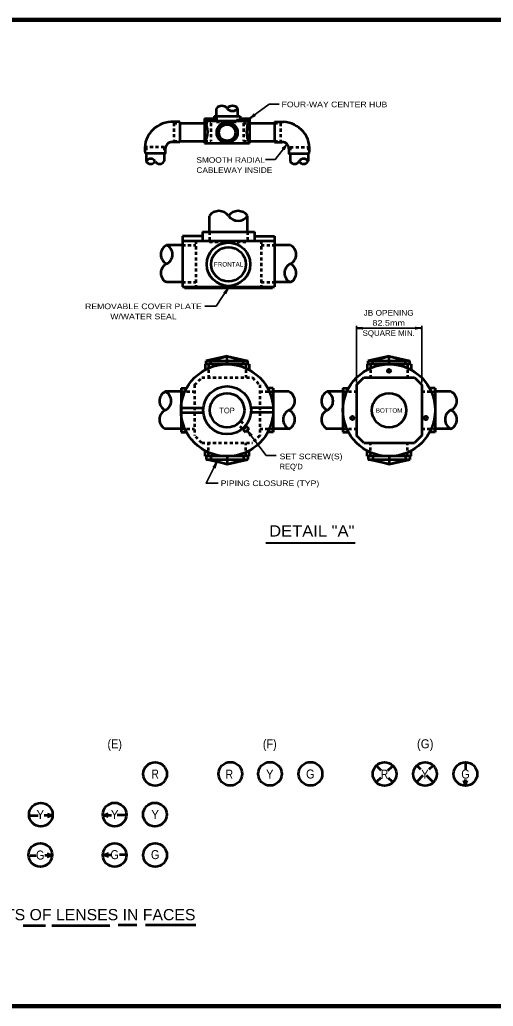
# Model space of a CAD drawing. Extents: x -382 to 473, y -132 to 412.
# Drawn here: x -79 to 174, y -120 to 406 of the extents above; entities that cross this region are included whole.
import ezdxf
from ezdxf.enums import TextEntityAlignment as Align

# ---------------------------------------------------------------- set-up
doc = ezdxf.new("R2010")
doc.units = 0
doc.header["$LTSCALE"] = 1.1
doc.linetypes.add('SHORT_DASHED', pattern=[2.7, 1.5, -1.2])
doc.layers.add('1', color=7, linetype='Continuous', lineweight=53)

msp = doc.modelspace()

# ---------------------------------------------------------------- linework, layer by layer
at = {"layer": '1'}
for p, q in [((26.07, 354.293), (26.07, 358.493)), ((37.47, 354.293), (37.47, 358.493)), ((19.77, 353.093), (19.77, 339.893)), ((19.77, 353.093), (24.87, 353.093)), ((24.87, 354.293), (38.67, 354.293)), ((24.87, 354.293), (24.87, 351.893)), ((38.67, 354.293), (38.67, 351.893)), ((38.67, 353.093), (43.77, 353.093)), ((43.77, 353.093), (43.77, 339.893)), ((6.57, 351.293), (1.77, 351.293)), ((6.57, 351.293), (6.57, 340.493)), ((6.57, 350.693), (19.77, 350.693)), ((19.77, 351.893), (43.77, 351.893)), ((43.77, 350.693), (56.97, 350.693)), ((56.97, 351.293), (56.97, 340.493)), ((56.97, 351.293), (61.77, 351.293)), ((6.57, 340.493), (2.37, 340.493)), ((6.57, 341.093), (19.77, 341.093)), ((19.77, 339.893), (43.77, 339.893)), ((43.77, 341.093), (56.97, 341.093)), ((56.97, 340.493), (61.17, 340.493)), ((-11.43, 334.493), (-11.43, 330.293)), ((-1.83, 334.493), (-1.83, 330.293)), ((65.37, 334.493), (65.37, 330.293)), ((74.97, 334.493), (74.97, 330.293)), ((22.298, 292.745), (22.298, 301.145)), ((42.698, 292.745), (42.698, 301.145)), ((18.698, 290.345), (7.898, 290.345)), ((7.898, 290.345), (7.898, 263.345)), ((18.698, 292.745), (46.298, 292.745)), ((18.698, 292.745), (18.698, 287.945)), ((46.298, 292.745), (46.298, 287.945)), ((46.298, 290.345), (57.098, 290.345)), ((57.098, 290.345), (57.098, 263.345)), ((7.898, 285.545), (-0.502, 285.545)), ((7.898, 287.945), (57.098, 287.945)), ((65.498, 285.545), (57.098, 285.545)), ((7.898, 265.745), (-0.502, 265.745)), ((7.898, 263.345), (57.098, 263.345)), ((9.098, 262.745), (9.098, 263.345)), ((55.898, 262.745), (55.898, 263.345)), ((65.498, 265.745), (57.098, 265.745)), ((9.098, 262.745), (55.898, 262.745)), ((31.77, 226.309), (42.87, 223.909)), ((118.17, 226.309), (129.27, 223.909)), ((20.07, 222.109), (20.07, 219.172)), ((43.47, 222.109), (20.07, 222.109)), ((20.67, 222.109), (20.67, 223.909)), ((20.67, 223.909), (42.87, 223.909)), ((23.07, 222.109), (23.07, 223.909)), ((40.47, 222.109), (40.47, 223.909)), ((42.87, 222.109), (42.87, 223.909)), ((43.47, 222.109), (43.47, 219.125)), ((106.47, 222.109), (106.47, 219.172)), ((129.87, 222.109), (106.47, 222.109)), ((107.07, 222.109), (107.07, 223.909)), ((107.07, 223.909), (129.27, 223.909)), ((109.47, 222.109), (109.47, 223.909)), ((126.87, 222.109), (126.87, 223.909)), ((129.27, 222.109), (129.27, 223.909)), ((129.87, 222.109), (129.87, 219.125)), ((100.77, 211.053), (104.67, 214.909)), ((100.77, 211.053), (100.77, 184.053)), ((104.67, 214.909), (131.67, 214.909)), ((131.67, 214.909), (135.57, 211.053)), ((135.57, 211.053), (135.57, 184.053)), ((7.17, 207.453), (-1.23, 207.453)), ((7.17, 209.253), (7.17, 185.853)), ((7.17, 209.253), (10.154, 209.253)), ((56.37, 209.253), (53.385, 209.253)), ((56.37, 209.253), (56.37, 185.853)), ((64.77, 207.453), (56.37, 207.453)), ((93.57, 207.453), (85.17, 207.453)), ((93.57, 209.253), (93.57, 185.853)), ((93.57, 209.253), (96.554, 209.253)), ((142.77, 209.253), (139.785, 209.253)), ((142.77, 209.253), (142.77, 185.853)), ((151.17, 207.453), (142.77, 207.453)), ((7.17, 198.753), (19.05, 198.753)), ((7.17, 196.353), (19.042, 196.353)), ((56.37, 198.753), (44.489, 198.753)), ((56.37, 196.353), (44.497, 196.353)), ((7.17, 187.653), (-1.23, 187.653)), ((7.17, 185.853), (10.106, 185.853)), ((40.457, 187.188), (39.949, 187.69)), ((42.142, 188.893), (40.351, 187.082)), ((40.351, 187.082), (41.631, 185.816)), ((41.543, 189.274), (42.036, 188.786)), ((43.422, 187.627), (41.631, 185.816)), ((42.142, 188.893), (43.422, 187.627)), ((56.37, 185.853), (53.433, 185.853)), ((64.77, 187.653), (56.37, 187.653)), ((93.57, 187.653), (85.17, 187.653)), ((93.57, 185.853), (96.506, 185.853)), ((142.77, 185.853), (139.833, 185.853)), ((151.17, 187.653), (142.77, 187.653)), ((104.67, 180.109), (100.77, 184.053)), ((104.67, 180.109), (131.67, 180.109)), ((135.57, 184.053), (131.67, 180.109)), ((20.07, 172.997), (20.07, 175.934)), ((43.47, 172.997), (43.47, 175.982)), ((106.47, 172.997), (106.47, 175.934)), ((129.87, 172.997), (129.87, 175.982)), ((43.47, 172.997), (20.07, 172.997)), ((20.67, 172.997), (20.67, 171.197)), ((20.67, 171.197), (42.87, 171.197)), ((23.07, 172.997), (23.07, 171.197)), ((31.77, 168.797), (42.87, 171.197)), ((40.47, 172.997), (40.47, 171.197)), ((42.87, 172.997), (42.87, 171.197)), ((129.87, 172.997), (106.47, 172.997)), ((107.07, 172.997), (107.07, 171.197)), ((107.07, 171.197), (129.27, 171.197)), ((109.47, 172.997), (109.47, 171.197)), ((118.17, 168.797), (129.27, 171.197)), ((126.87, 172.997), (126.87, 171.197)), ((129.27, 172.997), (129.27, 171.197)), ((113.875, 5.389), (111.724, 7.557)), ((117.509, 5.319), (119.79, 7.591)), ((135.053, 5.866), (133.126, 7.808)), ((139.614, 6.109), (141.443, 7.931)), ((158.929, 9.339), (158.929, 5.95)), ((111.706, -0.461), (113.873, 1.697)), ((119.738, -0.52), (117.938, 1.295)), ((133.102, -0.377), (136.417, 2.925)), ((141.438, -0.57), (138.074, 2.82)), ((158.929, -2.187), (158.109, 0.069)), ((158.929, -2.187), (158.929, 0.626)), ((158.929, -2.187), (159.75, 0.069)), ((-73.203, -18.622), (-69.003, -18.622)), ((-61.803, -18.622), (-65.899, -18.622)), ((-61.803, -18.622), (-64.058, -17.802)), ((-61.803, -18.622), (-64.058, -19.443)), ((-34.031, -18.362), (-31.776, -17.541)), ((-34.031, -18.362), (-29.935, -18.362)), ((-34.031, -18.362), (-31.776, -19.183)), ((-22.631, -18.362), (-26.831, -18.362)), ((-73.314, -39.92), (-70.048, -39.92)), ((-61.914, -39.92), (-65.466, -39.92)), ((-61.914, -39.92), (-64.169, -39.099)), ((-61.914, -39.92), (-64.169, -40.74)), ((-33.816, -39.555), (-31.561, -38.734)), ((-33.816, -39.555), (-30.264, -39.555)), ((-33.816, -39.555), (-31.561, -40.376)), ((-22.416, -39.555), (-25.682, -39.555)), ((-77.016, -77.252), (-65.149, -77.252)), ((-61.719, -77.252), (-30.799, -77.252)), ((-26.443, -76.94), (-16.449, -76.94)), ((-11.771, -76.94), (15.078, -76.94))]:
    msp.add_line(p, q, dxfattribs=at)
at = {"layer": '1', "linetype": 'SHORT_DASHED'}
for p, q in [((26.07, 354.293), (26.07, 351.293)), ((37.47, 351.293), (37.47, 354.293)), ((3.27, 350.693), (3.27, 341.093)), ((3.27, 350.693), (6.57, 350.693)), ((19.77, 350.693), (23.07, 350.693)), ((23.07, 350.693), (23.07, 341.093)), ((26.07, 351.293), (37.47, 351.293)), ((40.47, 350.693), (40.47, 341.093)), ((40.47, 350.693), (43.77, 350.693)), ((56.97, 350.693), (60.27, 350.693)), ((60.27, 350.693), (60.27, 341.093)), ((-1.83, 337.793), (-11.43, 337.793)), ((-11.43, 337.793), (-11.43, 334.493)), ((-1.83, 337.793), (-1.83, 334.493)), ((3.27, 341.093), (6.57, 341.093)), ((19.77, 341.093), (23.07, 341.093)), ((40.47, 341.093), (43.77, 341.093)), ((56.97, 341.093), (60.27, 341.093)), ((65.37, 337.793), (74.97, 337.793)), ((65.37, 337.793), (65.37, 334.493)), ((74.97, 337.793), (74.97, 334.493)), ((22.298, 292.745), (22.298, 287.345)), ((42.698, 292.745), (42.698, 287.345)), ((7.898, 285.545), (15.098, 285.545)), ((15.098, 287.945), (15.098, 263.345)), ((22.298, 287.345), (42.698, 287.345)), ((49.898, 287.945), (49.898, 263.345)), ((49.898, 285.545), (57.098, 285.545)), ((7.898, 265.745), (15.098, 265.745)), ((49.898, 265.745), (57.098, 265.745)), ((21.87, 222.109), (21.87, 214.909)), ((41.67, 222.109), (41.67, 214.909)), ((108.27, 222.109), (108.27, 214.909)), ((128.07, 222.109), (128.07, 214.909)), ((14.37, 211.053), (18.27, 214.909)), ((14.37, 211.053), (14.37, 184.053)), ((18.27, 214.909), (45.27, 214.909)), ((45.27, 214.909), (49.17, 211.053)), ((49.17, 211.053), (49.17, 184.053)), ((7.17, 207.453), (14.37, 207.453)), ((49.17, 207.453), (56.37, 207.453)), ((93.57, 207.453), (100.77, 207.453)), ((135.57, 207.453), (142.77, 207.453)), ((39.949, 187.69), (37.373, 190.237)), ((38.971, 191.816), (41.543, 189.274)), ((7.17, 187.653), (14.37, 187.653)), ((49.17, 187.653), (56.37, 187.653)), ((93.57, 187.653), (100.77, 187.653)), ((135.57, 187.653), (142.77, 187.653)), ((18.27, 180.109), (14.37, 184.053)), ((18.27, 180.109), (45.27, 180.109)), ((21.87, 172.997), (21.87, 180.197)), ((41.67, 172.997), (41.67, 180.197)), ((49.17, 184.053), (45.27, 180.109)), ((108.27, 172.997), (108.27, 180.197)), ((128.07, 172.997), (128.07, 180.197))]:
    msp.add_line(p, q, dxfattribs=at)
at = {"layer": '1', "lineweight": 35}
for p, q in [((100.77, 212.253), (100.77, 242.523)), ((135.57, 212.253), (135.57, 242.523)), ((100.77, 241.323), (135.57, 241.323))]:
    msp.add_line(p, q, dxfattribs=at)
at = {"layer": '1', "lineweight": 40}
msp.add_line((52.428, 126.853), (99.99, 126.853), dxfattribs=at)
at = {"layer": '1', "lineweight": 158}
msp.add_line((466.693, -120.327), (-324.907, -120.327), dxfattribs=at)
msp.add_lwpolyline([(466.693, 405.773), (-325.007, 405.673), (-324.907, -120.327)], dxfattribs=at)
at = {"layer": '1', "lineweight": 35}
for points in [[(43.77, 353.093), (54.269, 360.748), (59.576, 360.748)], [(63.73, 339.453), (57.321, 331.284), (52.279, 331.284)], [(32.355, 262.745), (25.831, 252.965), (19.823, 252.965)], [(42.526, 186.722), (52.628, 173.385), (57.998, 173.385)], [(26.22, 169.997), (20.552, 158.684), (27.052, 158.684)]]:
    msp.add_lwpolyline(points, dxfattribs=at)
at = {"layer": '1'}
for points in [[(-1.23, 336.893), (-1.23, 334.493), (-12.03, 334.493)], [(64.77, 336.893), (64.77, 334.493), (75.57, 334.493)], [(31.77, 222.109), (31.77, 226.309), (20.67, 223.909)], [(23.07, 223.909), (31.77, 226.309), (40.47, 223.909)], [(118.17, 222.109), (118.17, 226.309), (107.07, 223.909)], [(109.47, 223.909), (118.17, 226.309), (126.87, 223.909)], [(31.77, 172.997), (31.77, 168.797), (20.67, 171.197)], [(23.07, 171.197), (31.77, 168.797), (40.47, 171.197)], [(118.17, 172.997), (118.17, 168.797), (107.07, 171.197)], [(109.47, 171.197), (118.17, 168.797), (126.87, 171.197)]]:
    msp.add_lwpolyline(points, dxfattribs=at)
for centre, radius in [((31.77, 345.593), 5.58), ((31.77, 345.593), 4.38), ((32.498, 275.345), 11.58), ((32.498, 275.345), 9.18), ((31.77, 197.509), 24.6), ((118.17, 197.509), 24.6), ((118.17, 218.509), 0.9), ((31.77, 197.509), 12.78), ((31.77, 197.509), 9.18), ((118.17, 197.509), 9.18), ((98.562, 193.379), 0.9), ((137.777, 193.379), 0.9), ((-6.657, 3.512), 6.3), ((33.477, 3.626), 6.3), ((54.624, 3.626), 6.3), ((76.225, 3.626), 6.3), ((115.752, 3.554), 6.3), ((137.381, 3.554), 6.3), ((158.903, 3.554), 6.3), ((-67.621, -18.134), 6.3), ((-28.258, -18.096), 6.3), ((-6.77, -18.096), 6.3), ((-67.89, -39.609), 6.3), ((-28.258, -39.705), 6.3), ((-6.657, -39.705), 6.3)]:
    msp.add_circle(centre, radius, dxfattribs=at)
for centre, radius, start, end in [((28.92, 356.203), 3.656, 38.77886, 141.22114), ((34.62, 356.203), 3.656, 38.77886, 141.22114), ((34.62, 360.782), 3.656, 218.77886, 321.22114), ((2.294, 336.794), 14.508, 92.07061, 189.12807), ((9.686, 345.893), 11.734, 329.2475, 30.7525), ((53.854, 345.893), 11.734, 149.2475, 210.7525), ((61.245, 336.794), 14.508, 350.87193, 87.92939), ((2.319, 336.943), 3.55, 89.18565, 180.81435), ((61.22, 336.943), 3.55, 359.18565, 90.81435), ((-9.03, 328.913), 2.768, 29.89897, 150.10103), ((72.57, 328.913), 2.768, 29.89897, 150.10103), ((-9.03, 331.673), 2.768, 209.89897, 330.10103), ((-4.23, 331.673), 2.768, 209.89897, 330.10103), ((67.77, 331.673), 2.768, 209.89897, 330.10103), ((72.57, 331.673), 2.768, 209.89897, 330.10103), ((27.398, 297.514), 6.26, 35.44593, 144.55407), ((37.598, 297.514), 6.26, 35.44593, 144.55407), ((37.598, 304.775), 6.26, 215.44593, 324.55407), ((1.849, 280.595), 5.48, 115.40389, 244.59611), ((-2.853, 280.595), 5.48, 295.40389, 64.59611), ((63.147, 280.595), 5.48, 295.40389, 64.59611), ((1.849, 270.695), 5.48, 115.40389, 244.59611), ((67.849, 270.695), 5.48, 115.40389, 244.59611), ((63.147, 270.695), 5.48, 295.40389, 64.59611), ((1.12, 202.503), 5.48, 115.40389, 244.59611), ((-3.581, 202.503), 5.48, 295.40389, 64.59611), ((62.419, 202.503), 5.48, 295.40389, 64.59611), ((87.52, 202.503), 5.48, 115.40389, 244.59611), ((82.819, 202.503), 5.48, 295.40389, 64.59611), ((148.819, 202.503), 5.48, 295.40389, 64.59611), ((1.12, 192.603), 5.48, 115.40389, 244.59611), ((67.12, 192.603), 5.48, 115.40389, 244.59611), ((62.419, 192.603), 5.48, 295.40389, 64.59611), ((87.52, 192.603), 5.48, 115.40389, 244.59611), ((153.52, 192.603), 5.48, 115.40389, 244.59611), ((148.819, 192.603), 5.48, 295.40389, 64.59611)]:
    msp.add_arc(centre, radius, start, end, dxfattribs=at)
at = {"layer": '1', "lineweight": 40}
for centre, major_axis, ratio, start_param, end_param in [((44.632, 354.132), (-1.621, -1.414), 0.122415, 0.8963533, 3.1415927), ((45.006, 353.68), (-1.827, -1.071), 0.07063, 3.1407148, 5.41811), ((62.7, 338.552), (1.467, 1.528), 0.07063, 3.1407148, 5.41811), ((63.183, 338.218), (1.175, 1.802), 0.122415, 0.8963533, 3.1415927), ((31.353, 261.839), (1.345, 1.679), 0.122415, 3.1415927, 5.386832), ((31.82, 261.485), (0.994, 1.87), 0.07063, 0.8650754, 3.1424706), ((102.114, 241.069), (-2.108, 0.211), 0.07063, 3.1407148, 5.41811), ((102.114, 241.069), (-2.108, 0.211), 0.07063, 3.1407148, 5.41811), ((102.079, 241.654), (-2.143, -0.187), 0.122415, 0.8963533, 3.1415927), ((102.079, 241.654), (-2.143, -0.187), 0.122415, 0.8963533, 3.1415927), ((134.26, 240.991), (2.143, 0.187), 0.122415, 0.8963533, 3.1415927), ((134.225, 241.577), (2.108, -0.211), 0.07063, 3.1407148, 5.41811), ((43.136, 185.496), (-1.105, 1.807), 0.07063, 3.1407148, 5.41811), ((43.581, 185.878), (-1.443, 1.595), 0.122415, 0.8963533, 3.1415927), ((25.39, 168.909), (1.133, 1.79), 0.07063, 3.1407148, 5.41811), ((25.93, 168.678), (0.792, 2), 0.122415, 0.8963533, 3.1415927)]:
    msp.add_ellipse(centre, major_axis=major_axis, ratio=ratio, start_param=start_param, end_param=end_param, dxfattribs=at)

# ---------------------------------------------------------------- texts
at = {"layer": '1'}
for s, height, width, p in [('FOUR-WAY CENTER HUB', 3, 1.15, (89.031, 359.115)), ('FRONTAL', 2.4, 1.05, (32.545, 274.152)), ('REMOVABLE COVER PLATE', 3, 1.15, (-12.869, 251.43)), ('W/WATER SEAL', 3, 1.15, (-12.869, 246.03)), ('JB OPENING', 3, 1.1, (117.954, 247.972)), ('82.5mm', 3, 1.2, (117.954, 242.572)), ('SQUARE MIN.', 3, 1.05, (117.954, 237.172)), ('PIPING CLOSURE (TYP)', 3, 1.15, (54.634, 157.069)), ('DETAIL "A"', 6, 1.1, (76.938, 130.17)), ('(E)', 4.8, 0.9, (-28.212, 17.172)), ('(F)', 4.8, 0.9, (54.517, 17.164)), ('(G)', 4.8, 0.95, (137.45, 17.252)), ('R', 4.8, 0.85, (-6.649, 1.12)), ('R', 4.8, 0.85, (32.947, 1.021)), ('Y', 4.8, 0.95, (54.515, 1.133)), ('G', 4.8, 0.9, (76.14, 1.133)), ('R', 4.8, 0.85, (115.744, 1.076)), ('Y', 4.8, 0.95, (137.282, 1.131)), ('G', 4.8, 0.9, (158.929, 1.131)), ('Y', 4.8, 0.95, (-67.896, -20.491)), ('Y', 4.8, 0.95, (-28.251, -20.49)), ('Y', 4.8, 0.95, (-6.649, -20.49)), ('G', 4.8, 0.9, (-67.971, -42.091)), ('G', 4.8, 0.9, (-28.251, -41.859)), ('G', 4.8, 0.9, (-6.649, -41.859)), ('TYPICAL ARRANGEMENTS OF LENSES IN FACES', 6, 1.05, (-84.845, -74.459))]:
    msp.add_text(s, height=height, dxfattribs=dict(at, width=width)).set_placement(p, align=Align.CENTER)
for s, width, p in [('SMOOTH RADIAL', 1.1, (15.395, 329.478)), ('CABLEWAY INSIDE', 1.1, (15.395, 324.079)), ('SET SCREW(S)', 1.15, (59.747, 171.385))]:
    msp.add_text(s, height=3, dxfattribs=dict(at, width=width)).set_placement(p)
for s, height, p in [('TOP', 3, (31.708, 195.877)), ('BOTTOM', 2.4, (118.195, 196.215))]:
    msp.add_text(s, height=height, dxfattribs=at).set_placement(p, align=Align.CENTER)
msp.add_text("REQ'D", height=3, dxfattribs=at).set_placement((59.747, 165.985))

doc.saveas('drawing.dxf')
